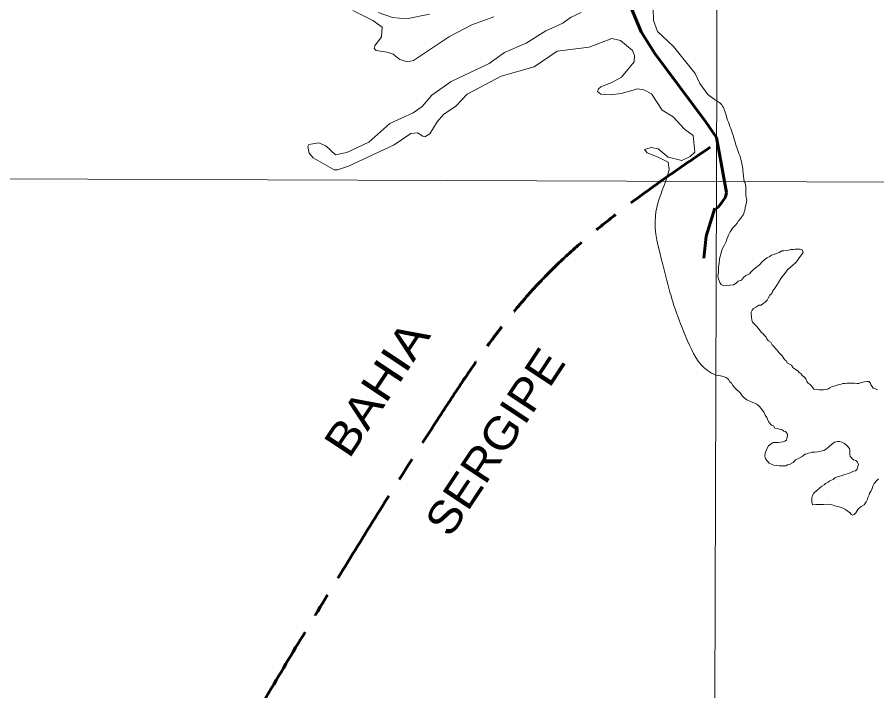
# Model space of a CAD drawing. Extents: x -1643653 to 4543381, y 1624270 to 13878484.
# Drawn here: x 601111 to 611751, y 8943403 to 8951740 of the extents above; entities that cross this region are included whole.
import ezdxf
from ezdxf.enums import TextEntityAlignment as Align

# ---------------------------------------------------------------- set-up
doc = ezdxf.new("R2010")
doc.units = 0
doc.header["$LTSCALE"] = 200
doc.linetypes.add('LONG_DASH_SHORT_DASH', pattern=[9.9, 6, -1.2, 1.5, -1.2])
for name, color, linetype, lineweight in [('1', 7, 'Continuous', 13), ('25', 7, 'Continuous', 13), ('57', 7, 'Continuous', 13), ('60', 7, 'Continuous', 13), ('7', 7, 'LONG_DASH_SHORT_DASH', 60)]:
    doc.layers.add(name, color=color, linetype=linetype, lineweight=lineweight)
doc.layers.add('42', color=7, linetype='Continuous')

msp = doc.modelspace()

# ---------------------------------------------------------------- linework, layer by layer
at = {"layer": '1'}
msp.add_line((565315.3, 8949866.8), (791497.7, 8949052.2), dxfattribs=at)
msp.add_lwpolyline([(609971.9, 9023551.8), (609764.7, 8949706.7), (609734.2, 8939404.4)], dxfattribs=at)
at = {"layer": '25'}
for points in [[(609755.4, 8950712.2), (609661.1, 8950783.5), (609561, 8950917.9), (609502.2, 8951042.1), (609232.8, 8951376.9), (609037.8, 8951563.3), (608987.2, 8951699.7), (608983.5, 8951846.5)], [(608090.2, 8951799.8), (607960.9, 8951735.6), (607862.5, 8951666.2), (607653, 8951570.5), (607410.8, 8951418.3), (607144.4, 8951302.6), (606950.8, 8951166.6), (606482.1, 8950942.3), (606242.9, 8950775.2), (606123, 8950635.5), (606012.1, 8950556.7), (605725, 8950424.5), (605463.8, 8950193.5), (605190.6, 8950065.5), (605051.5, 8950037.1), (604931.9, 8950147.3), (604842.4, 8950186), (604720.3, 8950162.6), (604710.1, 8950138.4)], [(605267.2, 8951822), (605514.5, 8951699.4), (605627.5, 8951614.5), (605620, 8951495.8), (605536.3, 8951386.5), (605528.7, 8951351.7), (605555.2, 8951329.8), (605690.4, 8951305.3), (605763.9, 8951283), (605848.8, 8951216.1), (605942.1, 8951185.6), (606018, 8951204.4), (606463.2, 8951500.4), (606738.6, 8951647.1), (607011.1, 8951745.5)], [(606213.2, 8951778.7), (605929, 8951719.6), (605757, 8951735), (605578.7, 8951796.6)], [(604710.1, 8950138.4), (604726.6, 8950056.6), (604775, 8950000.1), (604833.2, 8949967.4), (605034.8, 8949852), (605074.3, 8949852.1), (605210.6, 8949895.6), (605776.5, 8950159.4), (605984.7, 8950300.3), (606066, 8950310.7), (606133.6, 8950266.2), (606157.8, 8950260.8), (606219.7, 8950297.6), (606309.2, 8950444.5), (606386.8, 8950535.4), (606539, 8950640.6), (606679, 8950789), (607103.1, 8951009.8), (607511.4, 8951127.6), (607793.4, 8951318.1), (608189.8, 8951370), (608470.1, 8951476.1), (608576.2, 8951452.3), (608726.2, 8951326.4), (608749.8, 8951266.5), (608747.2, 8951186.9), (608590.8, 8950999.1), (608464.4, 8950928.1), (608333.9, 8950879.5), (608305.4, 8950852.7), (608293.4, 8950819), (608336.8, 8950788.8), (608450, 8950780.2), (608584.4, 8950796.9), (608792.8, 8950853.3), (608865.7, 8950839.8)], [(608865.7, 8950839.8), (608961.3, 8950792.2), (609092.6, 8950589), (609228.6, 8950508.5), (609370.6, 8950354.8), (609479, 8950274.1), (609498.7, 8950068.9), (609441.2, 8950017.2), (609336.6, 8949965), (609169.4, 8950008.4), (609042.6, 8950111.6), (608957.7, 8950128.6), (608874.2, 8950101.3), (608908.7, 8950059.5), (609044.9, 8950008.9), (609169.7, 8949947.6), (609179.8, 8949852.8), (609137, 8949702.7)], [(609792.6, 8948650.3), (609799.1, 8948692.7), (609802.3, 8948751.2), (609825.2, 8948822.9), (609838.2, 8948868.4), (609861, 8948914), (609887.1, 8948962.8), (609893.6, 8948992.1), (609916.4, 8949044.2), (609935.9, 8949083.3), (609968.5, 8949132.1), (610001.1, 8949167.9), (610023.9, 8949190.7), (610040.2, 8949220), (610069.5, 8949252.6), (610095.5, 8949294.9), (610115.1, 8949347), (610121.6, 8949382.8), (610134.6, 8949428.4), (610141.1, 8949473.9), (610130.7, 8949532.9), (610130.9, 8949558), (610131.1, 8949578), (610131.3, 8949608.1), (610129, 8949638.1), (610124.3, 8949673.2), (610117, 8949693.3), (610108.9, 8949704.2)], [(610788.6, 8947343.2), (610773.7, 8947363.3), (610741.4, 8947383.6), (610714, 8947401.3), (610696.7, 8947431.4), (610669.3, 8947444.1), (610646.9, 8947459.3), (610629.6, 8947486.9), (610607.2, 8947504.6), (610592.4, 8947527.2), (610577.6, 8947547.4), (610560.2, 8947570), (610537.9, 8947590.2), (610515.6, 8947617.9), (610498.2, 8947638), (610480.8, 8947658.2), (610456, 8947683.4), (610438.8, 8947716), (610408.9, 8947736.2), (610389.1, 8947758.9), (610381.7, 8947779), (610361.9, 8947799.2), (610342, 8947821.8), (610319.7, 8947842), (610299.9, 8947872.2), (610282.5, 8947892.3), (610265.2, 8947912.5), (610232.9, 8947945.2), (610213.1, 8947965.4), (610205.8, 8947990.5), (610198.6, 8948030.6), (610196.3, 8948068.1), (610196.5, 8948090.7), (610206.7, 8948113.1), (610224.4, 8948135.5), (610254.5, 8948152.9), (610292.2, 8948175.1), (610319.7, 8948175), (610342.4, 8948194.8), (610367.5, 8948214.7), (610395.2, 8948239.6), (610407.9, 8948264.5), (610425.7, 8948299.4), (610450.9, 8948321.8), (610458.6, 8948344.3), (610471.2, 8948366.7), (610493.9, 8948389.1), (610533.4, 8948456.2), (610564.5, 8948504.9), (610611, 8948567), (610646.5, 8948613.2), (610686.8, 8948650.5), (610711.9, 8948670.4), (610749.7, 8948705.2), (610767.4, 8948727.6), (610787.7, 8948760), (610807.8, 8948782.4), (610838.2, 8948827.3), (610825.9, 8948859.9), (610803.5, 8948870.1), (610771, 8948870.3), (610741, 8948868), (610720.9, 8948865.6), (610683.4, 8948863.3), (610663.3, 8948858.5), (610630.8, 8948853.7), (610600.7, 8948848.9), (610573.2, 8948846.6), (610540.6, 8948826.7), (610505.4, 8948814.5), (610475.3, 8948802.1), (610447.8, 8948794.8), (610427.6, 8948779.9), (610392.5, 8948762.6), (610372.4, 8948747.7), (610330.1, 8948712.2), (610330.1, 8948712.2), (610297.5, 8948676.4), (610297.5, 8948676.4), (610248.6, 8948637.3), (610219.3, 8948611.3), (610219.3, 8948611.3), (610193.3, 8948585.2), (610173.7, 8948562.4), (610128.1, 8948542.9), (610102.1, 8948520.1), (610076, 8948484.3), (610033.6, 8948471.3), (610010.8, 8948448.5), (609975, 8948429), (609932.7, 8948422.5), (609892.2, 8948420.5), (609854.5, 8948416), (609854.5, 8948416), (609825.2, 8948432.2), (609808.9, 8948458.3), (609808.9, 8948458.3), (609789.3, 8948500.6), (609782.8, 8948533.1), (609789.3, 8948588.5), (609792.6, 8948650.3)], [(609757.5, 8947308.3), (609815.9, 8947301.8), (609850.4, 8947294.2), (609884.9, 8947280.7), (609915.6, 8947253.9), (609930.9, 8947229), (609953.9, 8947209.9), (609969.3, 8947183), (609969.3, 8947183), (609998, 8947148.6), (609998, 8947148.6), (610019.1, 8947129.4), (610043.1, 8947109), (610060.4, 8947088.9), (610082.7, 8947053.7), (610107.5, 8947031), (610141.8, 8947004.9), (610141.8, 8947004.9), (610194.6, 8946980.4), (610227.1, 8946967.6), (610266.9, 8946949.8), (610299.2, 8946922.1), (610314.1, 8946902), (610331.5, 8946881.8), (610356.2, 8946846.6), (610368.5, 8946816.5), (610388.2, 8946783.8), (610395.6, 8946763.7), (610412.8, 8946728.6), (610445.1, 8946690.8), (610470, 8946680.6), (610487.3, 8946655.5), (610522.2, 8946647.7), (610554.7, 8946637.5), (610577.2, 8946632.3), (610599.6, 8946617.2), (610622, 8946612), (610644.3, 8946579.3), (610644.1, 8946556.8), (610638.9, 8946529.3), (610631.2, 8946504.3), (610614, 8946490.7), (610590.3, 8946484), (610556.5, 8946480.6), (610530.9, 8946474.9), (610500.9, 8946475.1), (610465.9, 8946475.4), (610443.3, 8946460.5), (610410.6, 8946433.2), (610390.3, 8946398.2), (610381.7, 8946376.9), (610369.3, 8946345.4), (610365.9, 8946308.2), (610374.9, 8946274.4), (610391.8, 8946250.7), (610418.9, 8946220.3), (610453.9, 8946205.1), (610476.3, 8946197.4), (610513.8, 8946189.6), (610543.8, 8946186.9), (610588.8, 8946186.6), (610626.3, 8946188.9), (610646.4, 8946201.3), (610679, 8946208.6), (610716.7, 8946228.3), (610744.4, 8946260.7), (610782.1, 8946278), (610819.7, 8946297.8), (610842.4, 8946315.1), (610862.5, 8946332.5), (610882.6, 8946337.4), (610902.6, 8946342.3), (610925.1, 8946347.1), (610945.2, 8946354.5), (610982.7, 8946356.8), (611020.3, 8946361.5), (611057.9, 8946368.8), (611095.5, 8946378.6), (611128.1, 8946395.9), (611150.8, 8946418.2), (611170.9, 8946435.6), (611206.2, 8946465.4), (611226.3, 8946480.3), (611263.9, 8946487.6), (611288.9, 8946487.4), (611316.3, 8946482), (611350.2, 8946462), (611380.9, 8946440.5), (611411.6, 8946402.2), (611411.6, 8946402.2), (611418.1, 8946381.4), (611417.9, 8946346.4), (611417.7, 8946326.4), (611420, 8946301.3), (611439.9, 8946281.2), (611462.2, 8946263.5), (611492.2, 8946253.3), (611513, 8946231.7), (611524.3, 8946205.5), (611516.6, 8946178), (611508.9, 8946148)], [(611759.9, 8947129), (611732.5, 8947141.7), (611705, 8947149.4), (611695.2, 8947169.4), (611675.3, 8947189.6), (611670.5, 8947209.7), (611650.6, 8947232.3), (611630.6, 8947230), (611598.1, 8947227.7), (611578, 8947222.8), (611558, 8947217.9), (611527.9, 8947208.1), (611507.9, 8947208.2), (611475.4, 8947208.5), (611445.4, 8947208.7), (611422.8, 8947208.8), (611400.3, 8947209), (611380.3, 8947209.1), (611357.8, 8947206.7), (611330.3, 8947204.4), (611310.2, 8947199.5), (611280.2, 8947192.2), (611252.6, 8947182.4), (611222.5, 8947175.1), (611199.9, 8947167.7), (611167.3, 8947152.9), (611144.7, 8947138.1), (611109.6, 8947130.8), (611089.6, 8947128.4), (611057.1, 8947128.6), (611037.1, 8947128.8), (611002.1, 8947134), (610972.1, 8947136.7), (610954.8, 8947159.3), (610925, 8947192.1), (610900.1, 8947212.3), (610882.8, 8947232.4), (610870.5, 8947262.5), (610855.7, 8947285.2), (610825.8, 8947305.4), (610813.5, 8947325.5), (610788.6, 8947343.2)], [(611508.9, 8946148), (611488.7, 8946125.6), (611461.2, 8946123.3), (611431, 8946103.4), (611398.4, 8946093.7), (611370.8, 8946083.8), (611340.8, 8946074), (611310.6, 8946061.7), (611265.6, 8946052), (611232.9, 8946037.2), (611210.3, 8946017.3), (611170.1, 8946000), (611150, 8945985.1), (611117.3, 8945967.8), (611097.2, 8945952.9), (611069.6, 8945935.6), (611039.4, 8945910.8), (611011.4, 8945885.7), (610972.4, 8945850.4), (610955.6, 8945820.6), (610948.2, 8945789), (610948.2, 8945789), (610948.2, 8945740.7), (610953.8, 8945703.5)], [(610953.8, 8945703.5), (610994.7, 8945707.2), (611046.8, 8945709.1), (611091.4, 8945707.2), (611139.8, 8945714.6), (611186.3, 8945707.2), (611231, 8945694.2), (611262.6, 8945684.9), (611284.9, 8945679.3), (611322.2, 8945668.2), (611322.2, 8945668.2), (611353.8, 8945651.4), (611378, 8945634.7), (611398.4, 8945619.8), (611422.6, 8945606.8), (611433.8, 8945586.3), (611452.4, 8945578.9), (611471, 8945584), (611491.2, 8945606.4), (611516.5, 8945646.3), (611536.7, 8945668.7), (611556.8, 8945686.1), (611594.5, 8945705.9), (611617.3, 8945743.3), (611635.1, 8945775.7), (611637.7, 8945795.7), (611658, 8945828.2), (611660.6, 8945848.2), (611678.3, 8945870.6), (611691.1, 8945905.5), (611701.3, 8945935.5), (611719.1, 8945967.9), (611749.3, 8946005.3), (611769.5, 8946025.2)]]:
    msp.add_lwpolyline(points, dxfattribs=at)
for points in [[(610108.9, 8949704.2), (610092.8, 8949844.8), (610081.3, 8949930.9), (610018.2, 8950125.9), (609960.9, 8950309.5), (609886.3, 8950521.8), (609817.5, 8950670.9), (609755.4, 8950712.2)], [(609137, 8949702.7), (609010, 8949279.3), (609102.4, 8948678.5), (609204.1, 8948290.3), (609407.4, 8947735.7), (609657, 8947365.9), (609757.5, 8947308.3)]]:
    msp.add_spline(points, degree=3, dxfattribs=at)
at = {"layer": '57'}
for points in [[(609755.4, 8950712.2), (609661.1, 8950783.5), (609561, 8950917.9), (609502.2, 8951042.1), (609232.8, 8951376.9), (609037.8, 8951563.3), (608987.2, 8951699.7), (608983.5, 8951846.5)], [(608983.5, 8951846.5), (608987.2, 8951699.7), (609037.8, 8951563.3), (609232.8, 8951376.9), (609502.2, 8951042.1), (609561, 8950917.9), (609661.1, 8950783.5), (609755.4, 8950712.2)], [(609792.6, 8948650.3), (609799.1, 8948692.7), (609802.3, 8948751.2), (609825.2, 8948822.9), (609838.2, 8948868.4), (609861, 8948914), (609887.1, 8948962.8), (609893.6, 8948992.1), (609916.4, 8949044.2), (609935.9, 8949083.3), (609968.5, 8949132.1), (610001.1, 8949167.9), (610023.9, 8949190.7), (610040.2, 8949220), (610069.5, 8949252.6), (610095.5, 8949294.9), (610115.1, 8949347), (610121.6, 8949382.8), (610134.6, 8949428.4), (610141.1, 8949473.9), (610130.7, 8949532.9), (610130.9, 8949558), (610131.1, 8949578), (610131.3, 8949608.1), (610129, 8949638.1), (610124.3, 8949673.2), (610117, 8949693.3), (610108.9, 8949704.2)], [(610108.9, 8949704.2), (610117, 8949693.3), (610124.3, 8949673.2), (610129, 8949638.1), (610131.3, 8949608.1), (610131.1, 8949578), (610130.9, 8949558), (610130.7, 8949532.9), (610141.1, 8949473.9), (610134.6, 8949428.4), (610121.6, 8949382.8), (610115.1, 8949347), (610095.5, 8949294.9), (610069.5, 8949252.6), (610040.2, 8949220), (610023.9, 8949190.7), (610001.1, 8949167.9), (609968.5, 8949132.1), (609935.9, 8949083.3), (609916.4, 8949044.2), (609893.6, 8948992.1), (609887.1, 8948962.8), (609861, 8948914), (609838.2, 8948868.4), (609825.2, 8948822.9), (609802.3, 8948751.2), (609799.1, 8948692.7), (609792.6, 8948650.3)], [(610788.6, 8947343.2), (610773.7, 8947363.3), (610741.4, 8947383.6), (610714, 8947401.3), (610696.7, 8947431.4), (610669.3, 8947444.1), (610646.9, 8947459.3), (610629.6, 8947486.9), (610607.2, 8947504.6), (610592.4, 8947527.2), (610577.6, 8947547.4), (610560.2, 8947570), (610537.9, 8947590.2), (610515.6, 8947617.9), (610498.2, 8947638), (610480.8, 8947658.2), (610456, 8947683.4), (610438.8, 8947716), (610408.9, 8947736.2), (610389.1, 8947758.9), (610381.7, 8947779), (610361.9, 8947799.2), (610342, 8947821.8), (610319.7, 8947842), (610299.9, 8947872.2), (610282.5, 8947892.3), (610265.2, 8947912.5), (610232.9, 8947945.2), (610213.1, 8947965.4), (610205.8, 8947990.5), (610198.6, 8948030.6), (610196.3, 8948068.1), (610196.5, 8948090.7), (610206.7, 8948113.1), (610224.4, 8948135.5), (610254.5, 8948152.9), (610292.2, 8948175.1), (610319.7, 8948175), (610342.4, 8948194.8), (610367.5, 8948214.7), (610395.2, 8948239.6), (610407.9, 8948264.5), (610425.7, 8948299.4), (610450.9, 8948321.8), (610458.6, 8948344.3), (610471.2, 8948366.7), (610493.9, 8948389.1), (610533.4, 8948456.2), (610564.5, 8948504.9), (610611, 8948567), (610646.5, 8948613.2), (610686.8, 8948650.5), (610711.9, 8948670.4), (610749.7, 8948705.2), (610767.4, 8948727.6), (610787.7, 8948760), (610807.8, 8948782.4), (610838.2, 8948827.3), (610825.9, 8948859.9), (610803.5, 8948870.1), (610771, 8948870.3), (610741, 8948868), (610720.9, 8948865.6), (610683.4, 8948863.3), (610663.3, 8948858.5), (610630.8, 8948853.7), (610600.7, 8948848.9), (610573.2, 8948846.6), (610540.6, 8948826.7), (610505.4, 8948814.5), (610475.3, 8948802.1), (610447.8, 8948794.8), (610427.6, 8948779.9), (610392.5, 8948762.6), (610372.4, 8948747.7), (610330.1, 8948712.2), (610330.1, 8948712.2), (610297.5, 8948676.4), (610297.5, 8948676.4), (610248.6, 8948637.3), (610219.3, 8948611.3), (610219.3, 8948611.3), (610193.3, 8948585.2), (610173.7, 8948562.4), (610128.1, 8948542.9), (610102.1, 8948520.1), (610076, 8948484.3), (610033.6, 8948471.3), (610010.8, 8948448.5), (609975, 8948429), (609932.7, 8948422.5), (609892.2, 8948420.5), (609854.5, 8948416), (609854.5, 8948416), (609825.2, 8948432.2), (609808.9, 8948458.3), (609808.9, 8948458.3), (609789.3, 8948500.6), (609782.8, 8948533.1), (609789.3, 8948588.5), (609792.6, 8948650.3)], [(609792.6, 8948650.3), (609789.3, 8948588.5), (609782.8, 8948533.1), (609789.3, 8948500.6), (609808.9, 8948458.3), (609808.9, 8948458.3), (609825.2, 8948432.2), (609854.5, 8948416), (609854.5, 8948416), (609892.2, 8948420.5), (609932.7, 8948422.5), (609975, 8948429), (610010.8, 8948448.5), (610033.6, 8948471.3), (610076, 8948484.3), (610102.1, 8948520.1), (610128.1, 8948542.9), (610173.7, 8948562.4), (610193.3, 8948585.2), (610219.3, 8948611.3), (610219.3, 8948611.3), (610248.6, 8948637.3), (610297.5, 8948676.4), (610297.5, 8948676.4), (610330.1, 8948712.2), (610330.1, 8948712.2), (610372.4, 8948747.7), (610392.5, 8948762.6), (610427.6, 8948779.9), (610447.8, 8948794.8), (610475.3, 8948802.1), (610505.4, 8948814.5), (610540.6, 8948826.7), (610573.2, 8948846.6), (610600.7, 8948848.9), (610630.8, 8948853.7), (610663.3, 8948858.5), (610683.4, 8948863.3), (610720.9, 8948865.6), (610741, 8948868), (610771, 8948870.3), (610803.5, 8948870.1), (610825.9, 8948859.9), (610838.2, 8948827.3), (610807.8, 8948782.4), (610787.7, 8948760), (610767.4, 8948727.6), (610749.7, 8948705.2), (610711.9, 8948670.4), (610686.8, 8948650.5), (610646.5, 8948613.2), (610611, 8948567), (610564.5, 8948504.9), (610533.4, 8948456.2), (610493.9, 8948389.1), (610471.2, 8948366.7), (610458.6, 8948344.3), (610450.9, 8948321.8), (610425.7, 8948299.4), (610407.9, 8948264.5), (610395.2, 8948239.6), (610367.5, 8948214.7), (610342.4, 8948194.8), (610319.7, 8948175), (610292.2, 8948175.1), (610254.5, 8948152.9), (610224.4, 8948135.5), (610206.7, 8948113.1), (610196.5, 8948090.7), (610196.3, 8948068.1), (610198.6, 8948030.6), (610205.8, 8947990.5), (610213.1, 8947965.4), (610232.9, 8947945.2), (610265.2, 8947912.5), (610282.5, 8947892.3), (610299.9, 8947872.2), (610319.7, 8947842), (610342, 8947821.8), (610361.9, 8947799.2), (610381.7, 8947779), (610389.1, 8947758.9), (610408.9, 8947736.2), (610438.8, 8947716), (610456, 8947683.4), (610480.8, 8947658.2), (610498.2, 8947638), (610515.6, 8947617.9), (610537.9, 8947590.2), (610560.2, 8947570), (610577.6, 8947547.4), (610592.4, 8947527.2), (610607.2, 8947504.6), (610629.6, 8947486.9), (610646.9, 8947459.3), (610669.3, 8947444.1), (610696.7, 8947431.4), (610714, 8947401.3), (610741.4, 8947383.6), (610773.7, 8947363.3), (610788.6, 8947343.2)], [(611759.9, 8947129), (611732.5, 8947141.7), (611705, 8947149.4), (611695.2, 8947169.4), (611675.3, 8947189.6), (611670.5, 8947209.7), (611650.6, 8947232.3), (611630.6, 8947230), (611598.1, 8947227.7), (611578, 8947222.8), (611558, 8947217.9), (611527.9, 8947208.1), (611507.9, 8947208.2), (611475.4, 8947208.5), (611445.4, 8947208.7), (611422.8, 8947208.8), (611400.3, 8947209), (611380.3, 8947209.1), (611357.8, 8947206.7), (611330.3, 8947204.4), (611310.2, 8947199.5), (611280.2, 8947192.2), (611252.6, 8947182.4), (611222.5, 8947175.1), (611199.9, 8947167.7), (611167.3, 8947152.9), (611144.7, 8947138.1), (611109.6, 8947130.8), (611089.6, 8947128.4), (611057.1, 8947128.6), (611037.1, 8947128.8), (611002.1, 8947134), (610972.1, 8947136.7), (610954.8, 8947159.3), (610925, 8947192.1), (610900.1, 8947212.3), (610882.8, 8947232.4), (610870.5, 8947262.5), (610855.7, 8947285.2), (610825.8, 8947305.4), (610813.5, 8947325.5), (610788.6, 8947343.2)], [(610788.6, 8947343.2), (610813.5, 8947325.5), (610825.8, 8947305.4), (610855.7, 8947285.2), (610870.5, 8947262.5), (610882.8, 8947232.4), (610900.1, 8947212.3), (610925, 8947192.1), (610954.8, 8947159.3), (610972.1, 8947136.7), (611002.1, 8947134), (611037.1, 8947128.8), (611057.1, 8947128.6), (611089.6, 8947128.4), (611109.6, 8947130.8), (611144.7, 8947138.1), (611167.3, 8947152.9), (611199.9, 8947167.7), (611222.5, 8947175.1), (611252.6, 8947182.4), (611280.2, 8947192.2), (611310.2, 8947199.5), (611330.3, 8947204.4), (611357.8, 8947206.7), (611380.3, 8947209.1), (611400.3, 8947209), (611422.8, 8947208.8), (611445.4, 8947208.7), (611475.4, 8947208.5), (611507.9, 8947208.2), (611527.9, 8947208.1), (611558, 8947217.9), (611578, 8947222.8), (611598.1, 8947227.7), (611630.6, 8947230), (611650.6, 8947232.3), (611670.5, 8947209.7), (611675.3, 8947189.6), (611695.2, 8947169.4), (611705, 8947149.4), (611732.5, 8947141.7), (611759.9, 8947129)]]:
    msp.add_lwpolyline(points, dxfattribs=at)
for points in [[(610108.9, 8949704.2), (610092.8, 8949844.8), (610081.3, 8949930.9), (610018.2, 8950125.9), (609960.9, 8950309.5), (609886.3, 8950521.8), (609817.5, 8950670.9), (609755.4, 8950712.2)], [(609755.4, 8950712.2), (609817.5, 8950670.9), (609886.3, 8950521.8), (609960.9, 8950309.5), (610018.2, 8950125.9), (610081.3, 8949930.9), (610092.8, 8949844.8), (610108.9, 8949704.2)]]:
    msp.add_spline(points, degree=3, dxfattribs=at)
at = {"layer": '60', "lineweight": 25}
msp.add_spline([(814781, 9009175.5), (814787.2, 9009173.4), (814796.9, 9009173.4), (814799.4, 9009172.4), (814805.1, 9009174.5), (814805.6, 9009176.5), (814811.7, 9009179.5), (814811.7, 9009179.5), (814801.5, 9009181), (814790.7, 9009181.5), (814784.1, 9009183.1), (814777.4, 9009185.1), (814778.4, 9009175.5)], degree=3, dxfattribs=at)
at = {"layer": '7'}
for points in [[(608709, 8951855.3), (608834.6, 8951559), (609001.1, 8951288.7), (609632.1, 8950450.2), (609766.1, 8950251.3)], [(609766.1, 8950251.3), (609892.1, 8949571.8), (609876.7, 8949511.8), (609848.8, 8949469.3), (609818.6, 8949432), (609785.7, 8949389.6), (609763.6, 8949371.8)], [(609608.9, 8948758.3), (609638.2, 8949029.6), (609745.9, 8949377.2)]]:
    msp.add_lwpolyline(points, dxfattribs=at)
msp.add_spline([(609688.1, 8950131.7), (607584.3, 8948466.4), (606301.7, 8946741.8), (602418.3, 8940294.4)], degree=3, dxfattribs=at)

# ---------------------------------------------------------------- texts
at = {"layer": '42'}
for s, width, p in [('BAHIA', 1.15, (605729.2, 8947032.4)), ('SERGIPE', 1.1, (607190.8, 8946373.9))]:
    msp.add_text(s, height=400, rotation=56.48, dxfattribs=dict(at, width=width)).set_placement(p, align=Align.CENTER)

doc.saveas('drawing.dxf')
